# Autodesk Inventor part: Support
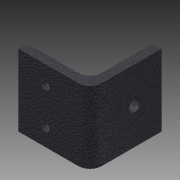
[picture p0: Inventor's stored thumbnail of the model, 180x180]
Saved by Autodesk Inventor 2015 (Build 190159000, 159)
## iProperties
Created: 2013-01
Part Number: Support
Material: Iron, Cast
Document SubType Name: Modeling
Designer: CADCIM
Density: 7.25 g/cm^3
Appearance: Iron - Cast
Mass: 106.214 g
Surface Area: 70.4217 cm^2
Volume: 14.6503 cm^3
Author: CADCIM
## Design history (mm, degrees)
sketch "Sketch1"
  geometry: L1 (0, 0)-(33.5, 0); L2 (40, 6.5)-(40, 40); L3 (40, 40)-(35, 40); L4 (35, 40)-(35, 11.5); L5 (28.5, 5)-(0, 5); L6 (0, 5)-(0, 0); A1 r 6.5 centre (33.5, 6.5) between (33.5, 0) and (40, 6.5); A2 r 6.5 centre (28.5, 11.5) between (28.5, 5) and (35, 11.5); 2 further points
  constraints: 12 end point, 4 point on circle, 4 point on line, 4 tangent, 3 perpendicular, 2 centre point, 2 parallel, 1 horizontal
  dimensions: "d0" = 40 distance of L1.start point (40, 0); "d2" = 40 distance of point (40, 0) L2.end; "d3" = 5 distance of L2.end L3.end; "d4" = 35 distance of L3.end point (35, 5); "d5" = 6.5 radius of A1; "d6" = 6.5 radius of A2
extrude "Extrusion1" new body sketch "Sketch1" distance "d7" = 40; taper "d8" = 0 deg
hole "Hole1" diameter "d11" = 5; stored, may be unused: countersink angle "d15" = 90 deg, drill point angle "d17" = 118 deg; dims "d9" = 10, "d10" = 15, "d12" = 6, "d13" = 4, "d14" = 2, "d16" = 8
pattern_linear "Rectangular Pattern1" dims "d20" = 20
hole "Hole2" diameter "d23" = 6.25; stored, may be unused: countersink angle "d27" = 90 deg, drill point angle "d29" = 118 deg; dims "d21" = 15, "d22" = 20, "d24" = 6, "d25" = 4, "d26" = 2, "d28" = 8
body "Solid1"
